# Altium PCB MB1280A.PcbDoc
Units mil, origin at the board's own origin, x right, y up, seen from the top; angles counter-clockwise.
Board outline 2150 x 1780 mil, 2 copper layers (Top Layer, Bottom Layer), stack 61.855 mil thick; 27 components, 23 nets, 119 pads, 19 vias.
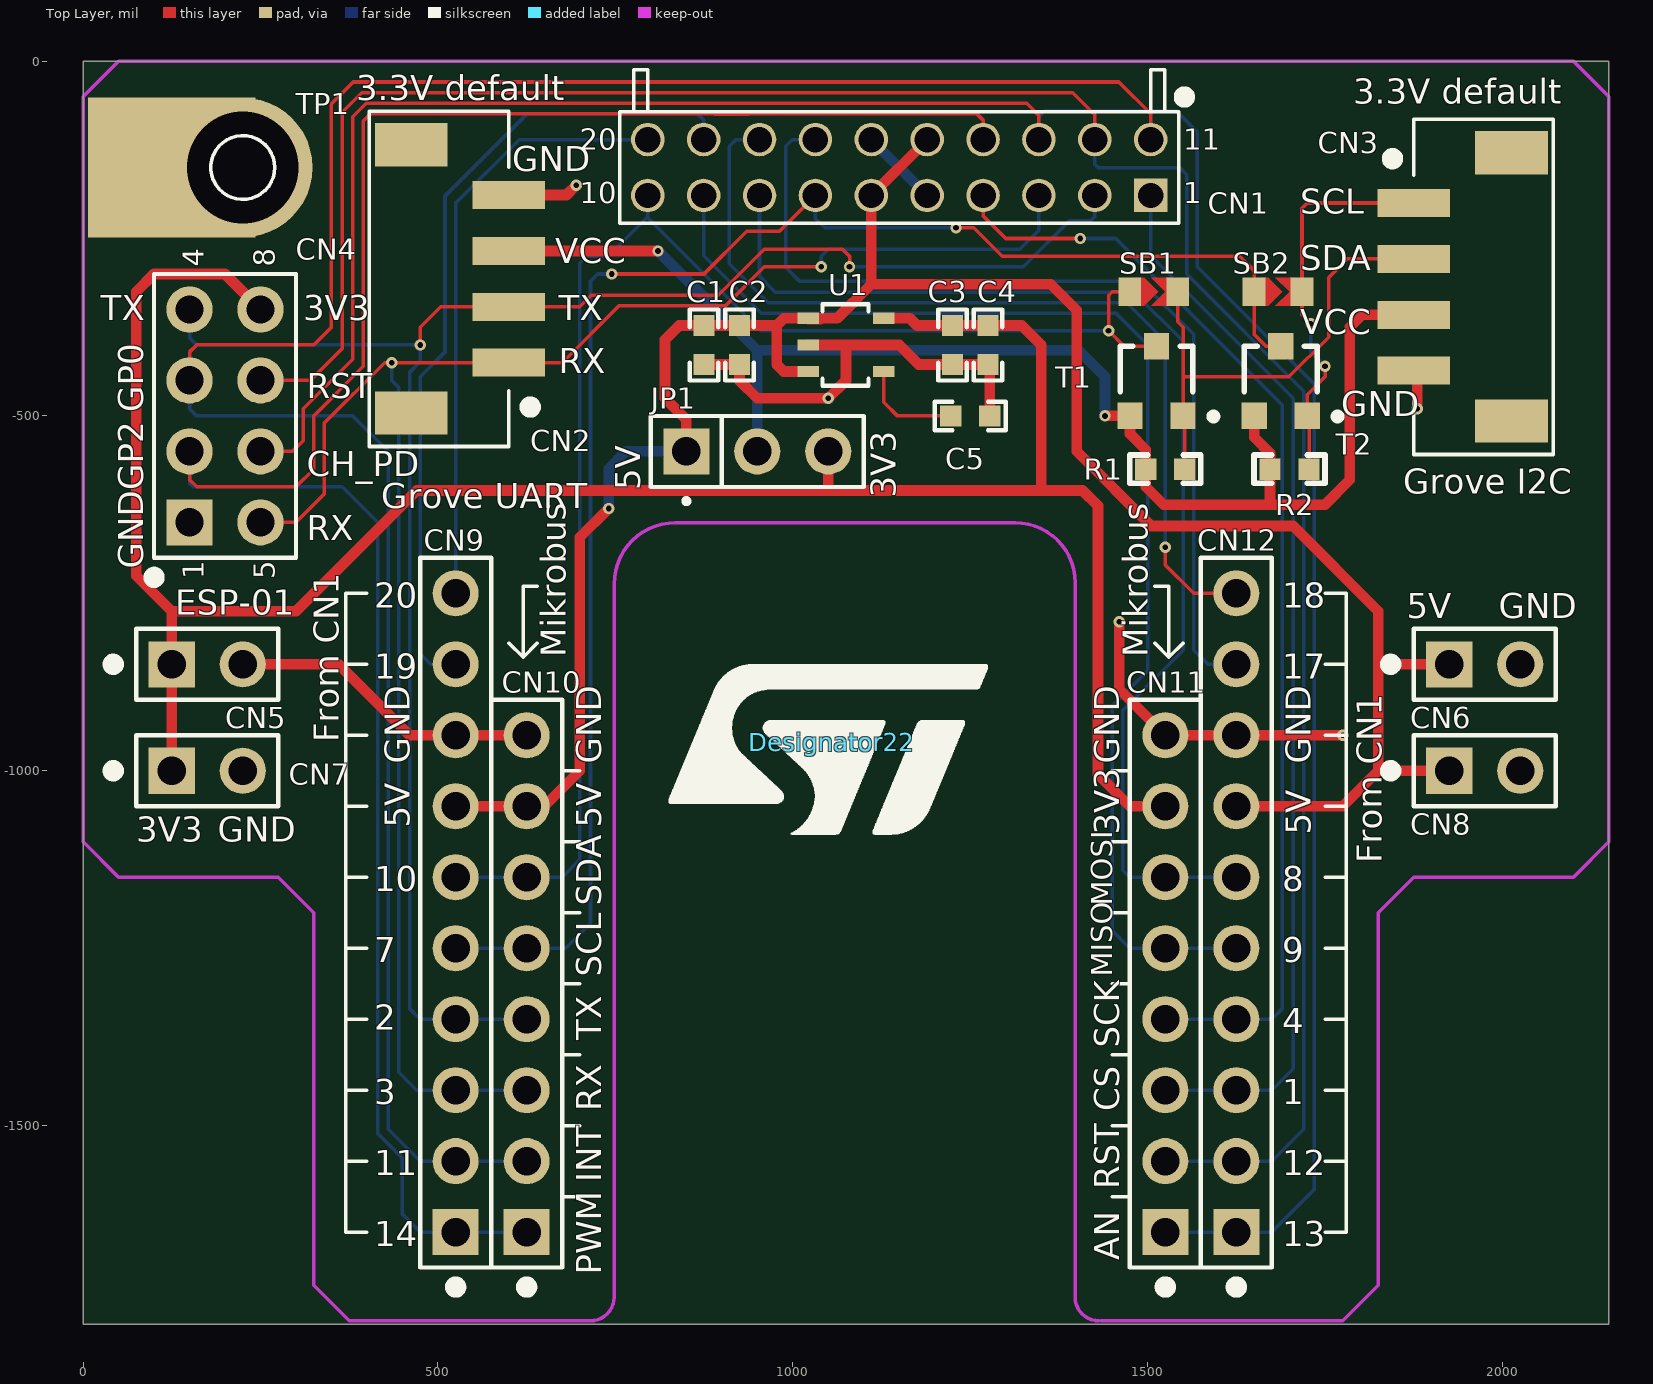
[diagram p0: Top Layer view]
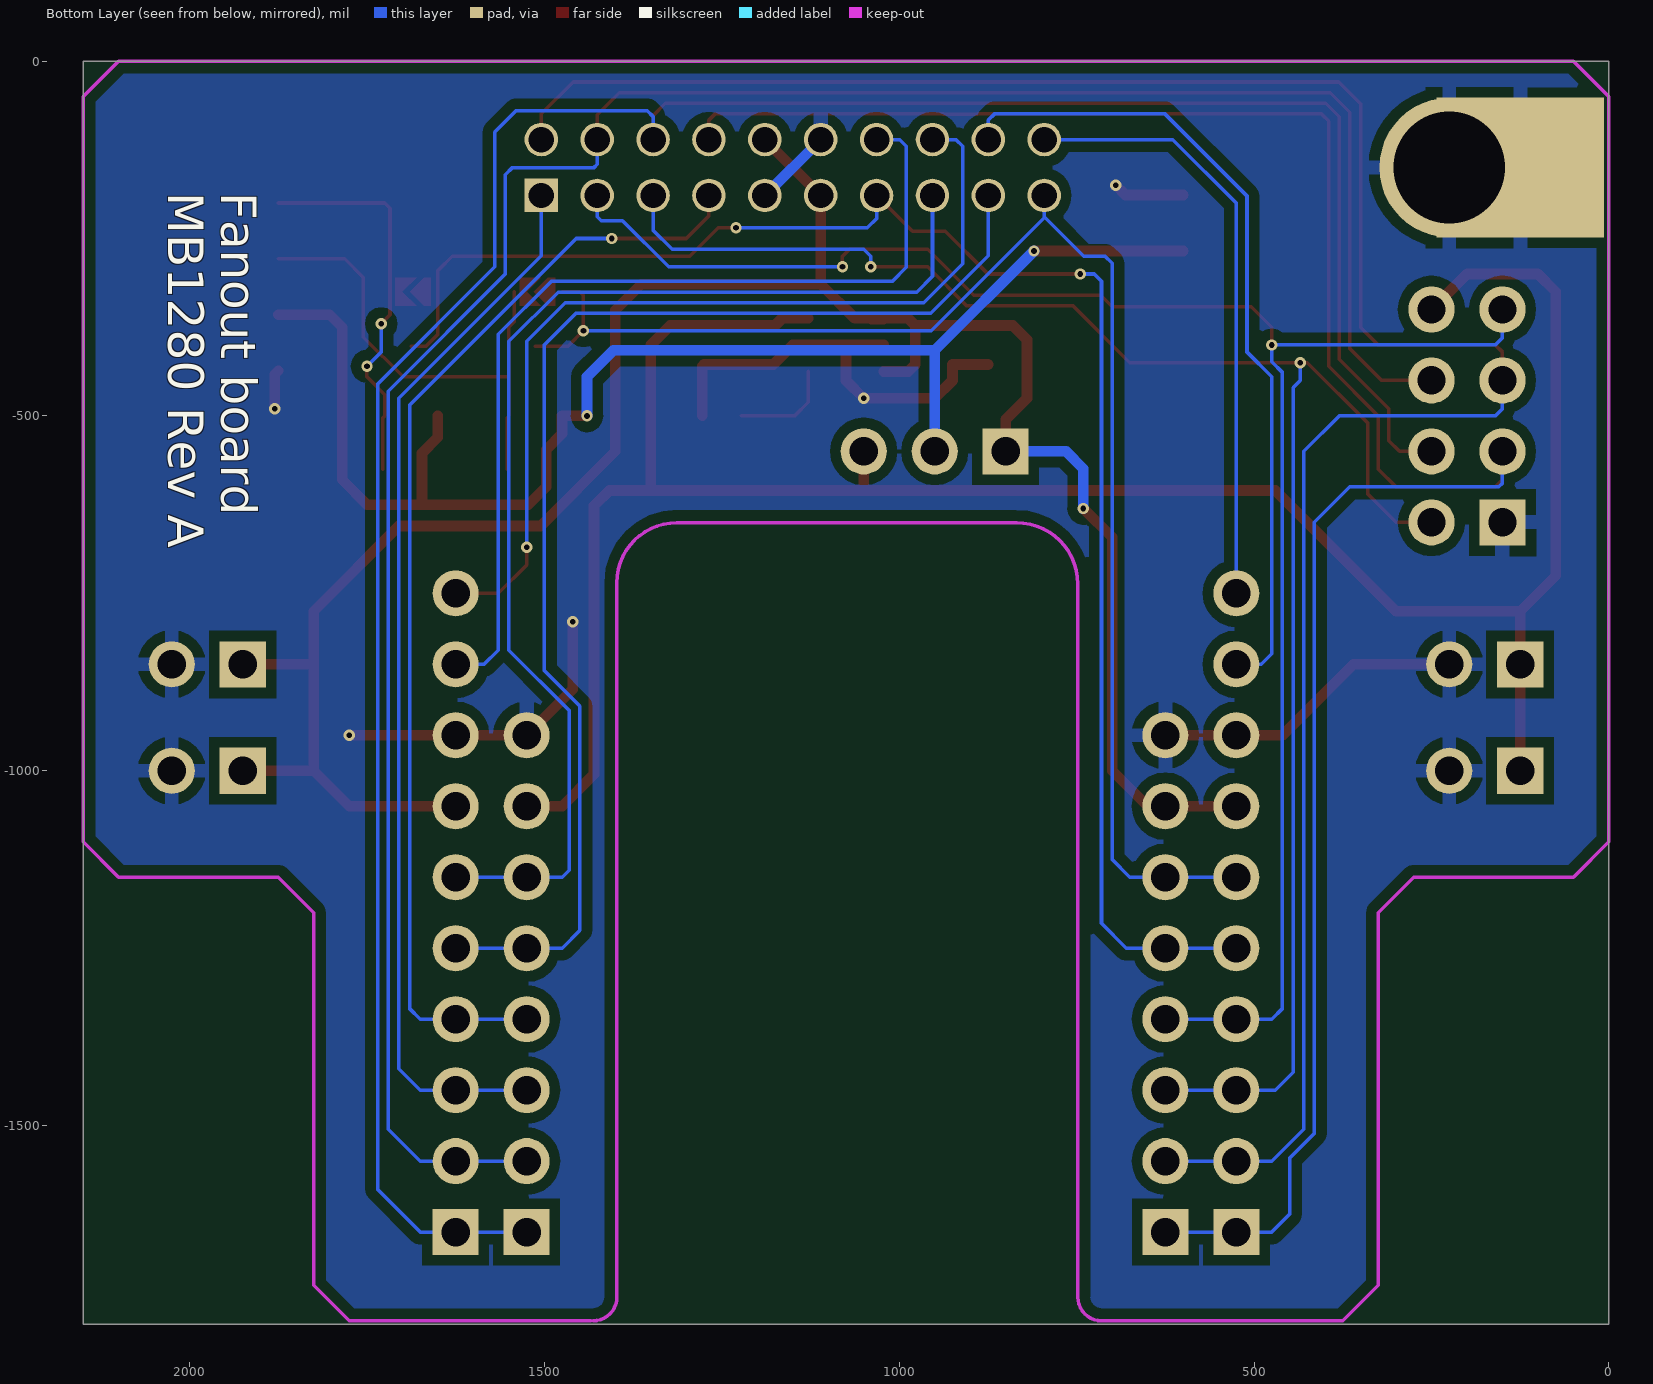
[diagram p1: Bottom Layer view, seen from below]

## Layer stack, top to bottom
Top Solder: solder mask 0.4, Solder Resist, Dk 3.5
Top Layer: signal copper 1.4
Dielectric1: core 59.0551, FR-4, Dk 4.8
Bottom Layer: signal copper 1.4
Bottom Solder: solder mask 0.4, Solder Resist, Dk 3.5

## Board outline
0,0 0,-1100 0,-1780 0,0 2150,0 2150,-1780 1290,-1780 0,-1780

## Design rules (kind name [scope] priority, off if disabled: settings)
Clearance Clearance_1 [(InPoly)] p1: gap=15
Clearance Clearance_2 [(HasFootprint('SB_DIP')) or (HasFootprint('JP2_SMD')) or InNet('PC13')] p2: gap=5
Clearance [All] p3: gap=10
FabricationTestPointUsage TestPointUsage [All] p1: valid=0 allowmultiple=FALSE
FabricationTestpoint Testpoint [(IsPad And (OnTopLayer Or OnBottomLayer))] p1: side=3 testpointundercomponent=TRUE minsize=40 maxsize=100 preferedsize=60 minholesize=0 maxholesize=40 preferedholesize=32 testpointgrid=1 allowsidetop=TRUE allowsidebottom=TRUE usegrid=TRUE gridtolerance=0.01
HoleSize [All] p1: absolutevalues=TRUE maxlimit=150 minlimit=1 maxpercent=80.000 minpercent=20.000
PolygonConnect PolygonConnect_1 [IsVia] p1: connectstyle=Direct reliefconductorwidth=20 reliefentries=4 polygonreliefangle="90 Angle" airgapwidth=10
PolygonConnect [All] p2: connectstyle=Relief reliefconductorwidth=20 reliefentries=4 polygonreliefangle="90 Angle" airgapwidth=10
RoutingLayers [All] p1: top layer_v5=FALSE bottom layer_v5=FALSE
RoutingVias [All] p1: holewidth=13 width=25 viastyle="Through Hole" minholewidth=8 minwidth=16 maxholewidth=28 maxwidth=50
SilkToSolderMaskClearance SilkscreenOverComponentPads [IsPad] p1: minsilkscreentomaskgap=10 clearancetoexposedcopper=TRUE
SolderMaskExpansion [All] p1: expansion=4
Width Width_1 [InNet('VDD_MCU')] p1: maxlimit=100 minlimit=6 preferedwidth=12
Width [All] p2: maxlimit=100 minlimit=5 preferedwidth=5 minimp=50.000000 maximp=50.000000 favimp=50.000000
25 further rules are at their usual default settings.

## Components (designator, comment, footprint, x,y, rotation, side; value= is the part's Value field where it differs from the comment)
C1 "100nF" 0603C 875,-400 r270 top (schematic designator C3)
C2 "1uF_X5R_0603" 0603C 925,-400 r270 top (schematic designator C1)
C3 "1uF_X5R_0603" 0603C 1225,-400 r90 top (schematic designator C2)
C4 "100nF" 0603C 1275,-400 r270 top
C5 "10nF_X7R_0603" 0603C 1250,-500 r0 top
CN1 "TMM-110-01-L-D-RA" 2*10_MALE_2MM_H 1150,-150 r0 top
CN2 "1125S-SMT-4P" 1X4_MALE_C 600,-425 r270 top (schematic designator CN10)
CN3 "1125S-SMT-4P" 1X4_MALE_C 1875,-200 r90 top (schematic designator CN2)
CN4 "Header 4X2A" HDR2X4_CEN1 150,-650 r90 top (schematic designator CN6)
CN5 "PAD 2" HDR_2X1_2R54 125,-850 r0 top
CN6 "PAD 2" HDR_2X1_2R54 1925,-850 r0 top (schematic designator CN7)
CN7 "PAD 2" HDR_2X1_2R54 125,-1000 r0 top (schematic designator CN11)
CN8 "PAD 2" HDR_2X1_2R54 1925,-1000 r0 top (schematic designator CN12)
CN9 "PAD 1X8" 1*10P_FEMALE 525,-1650 r90 top (schematic designator CN4)
CN10 "Header 8X1_Female" 1*8P_FEMALE 625,-1650 r90 top (schematic designator CN9)
CN11 "Header 8X1_Female" 1*8P_FEMALE 1525,-1650 r90 top (schematic designator CN8)
CN12 "PAD 1X8" 1*10P_FEMALE 1625,-1650 r90 top (schematic designator CN3)
Designator22 "Comment" ST_LOGO_10mm 1055,-960 r0 top
JP1 "" SIP3 850,-550 r0 top
R1 "4K7[N/A]" 0603R 1525,-575 r0 top
R2 "4K7[N/A]" 0603R 1700,-575 r0 top
SB1 "Closed" SB_0603 1475,-325 r180 top (schematic designator SB2)
SB2 "Closed" SB_0603 1650,-325 r180 top (schematic designator SB1)
T1 "BSN20[N/A]" SOT23-213 1550,-500 r0 top (schematic designator TR2)
T2 "BSN20[N/A]" SOT23-213 1725,-500 r0 top (schematic designator TR1)
TP1 "Ground" TP_C4MM_PAD 225,-150 r0 top
U1 "LDK120M33R" SOT-23-5L 1075,-400 r0 top

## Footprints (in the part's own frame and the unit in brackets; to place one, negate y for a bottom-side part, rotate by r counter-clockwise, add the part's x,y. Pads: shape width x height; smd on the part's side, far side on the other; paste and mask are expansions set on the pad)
1*8P_FEMALE [mil]
  rect 65x65 hole 40: 1(0,0)
  round 65 hole 40: 2(100,0) 3(200,0) 4(300,0) 5(400,0) 6(500,0) 7(600,0) 8(700,0)
  silkscreen extent -85,-50 750,50
1*10P_FEMALE [mil]
  rect 65x65 hole 40: 1(0,0)
  round 65 hole 40: 2(100,0) 3(200,0) 4(300,0) 5(400,0) 6(500,0) 7(600,0) 8(700,0) 9(800,0) 10(900,0)
  silkscreen extent -85,-50 950,50
1X4_MALE_C [mm] "Connector; Header; 4 Position"
  rect 1.55x2.6 smd: 0(-7.8,-3.5) 0(1.8,-3.5)
  rect 1x2.6 smd: 1(0,0) 2(-2,0) 3(-4,0) 4(-6,0)
  silkscreen extent -9,-5 3,0.95
2*10_MALE_2MM_H [mm]
  rect 1.2x1.2 hole 0.91: 1(9,-1)
  round 1.2 hole 0.91: 2(7,-1) 3(5,-1) 4(3,-1) 5(1,-1) 6(-1,-1) 7(-3,-1) 8(-5,-1) 9(-7,-1) 10(-9,-1) 11(9,1) 12(7,1) 13(5,1) 14(3,1) 15(1,1) 16(-1,1) 17(-3,1) 18(-5,1) 19(-7,1) 20(-9,1)
  silkscreen extent -10,-2 10.4,3.5
0603C [mil]
  rect 30x30 smd: 1(27.5,0) 2(-27.5,0)
  silkscreen extent -50,-20 50,20
0603R [mil]
  rect 30x30 smd: 1(27.5,0) 2(-27.5,0)
  silkscreen extent -50,-20 50,20
HDR2X4_CEN1 [mil] "Connector; Header; 4x2 Position"
  rect 65x65 hole 40: 1(0,0)
  round 65 hole 40: 2(100,0) 3(200,0) 4(300,0) 5(0,-100) 6(100,-100) 7(200,-100) 8(300,-100)
  silkscreen extent -85,-150 350,57
HDR_2X1_2R54 [mil]
  rect 65x65 hole 40: 1(0,0)
  round 65 hole 40: 2(100,0)
  silkscreen extent -90,-50 150,50
SB_0603 [mil]
  rect 32x40 smd: 1(0,0) 2(-67.5,0)
  Top Layer region: -10,20 -20,20 -40,0 -20,-20 -10,-20
  Top Layer region: -60,0 -50,0 -30,20 -60,20
  Top Layer region: -60,0 -50,0 -30,-20 -60,-20
SIP3 [mil]
  rect 65x65 hole 40: 1(0,0)
  round 65 hole 40: 2(100,0) 3(200,0)
  silkscreen extent -50,-72 250,50
SOT23-213 [mm]
  rect 0.9x0.95 smd: 1(0,0) 2(-1.9,0) 3(-0.95,2.5)
  silkscreen extent -2.25,-0.14 1.21,2.5
SOT-23-5L [mil]
  rect 30x16 smd: 1(-53.15,37.4) 2(-53.15,0) 3(-53.15,-37.4) 4(53.15,-37.4) 5(53.15,37.4)
  silkscreen extent -33,-58 32,57
ST_LOGO_10mm [mil]
  silkscreen extent -230,-130 220,110
TP_C4MM_PAD [mm]
  rect 6x5 smd: 1(-2.54,0)
  rect 6x5 smd far side: 1(-2.54,0)
  round 5 hole 4: 1(0,0)
  silkscreen extent -1.14,-1.14 1.14,1.14

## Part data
C1 C4: library part Capacitor_ST, "Capacitor 0402 / 0603 / 0805"
C2 C3: library part "CAP SMD 0603  X5R 1µF 25V 10%", "0603  X5R 1?"
C5: library part "CAP SMD 0603  X7R 10000PF 50V 10%", "0603  X7R 10NF"
CN1: library part "Header 10X2A", "Header, 10-Pin, Dual row"
CN2 CN3: library part "Header 4"
CN4: "Header, 4-Pin, Dual row"
CN5 CN6 CN7 CN8: library part "Header 2", "Header, 2-Pin"
CN9 CN12: library part "Header 10X1_Female", "Header, 10-Pin, Single row,female"
CN10 CN11: "Header, 8-Pin, Single row,female"
JP1: library part Jumper3
R1 R2: library part res1, "Resistor"
SB1 SB2: library part "Circuit Breaker", "Circuit Breaker"
T1 T2: library part 2N7000
TP1: library part TP
U1: "200 mA low quiescent current very low noise LDO"

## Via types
v1: diameter 16, hole 8, Top Layer to Bottom Layer, tented both sides, 19 vias

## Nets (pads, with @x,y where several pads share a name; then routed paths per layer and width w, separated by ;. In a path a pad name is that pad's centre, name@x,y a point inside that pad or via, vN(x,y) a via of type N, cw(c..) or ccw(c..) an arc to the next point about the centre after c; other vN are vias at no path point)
+3V3: C3.1 C4.2 CN4.8 CN5.1 CN7.1 CN11.7 JP1.3 U1.5 | length 3275.5
  Top Layer w15: CN7.1 CN5.1 125,-775 ; CN4.8 200,-300 100,-300 75,-325 75,-725 125,-775 ; JP1.3 1050,-605 ; U1.5 1165.1,-362.6 1175,-372.5 C3.1 C4.2 1322.5,-372.5 1350,-400 1350,-605 ; CN11.7 1475,-1050 1430,-1005 1430,-626.72 1408.28,-605 1350,-605 ; 125,-775 300,-775 470,-605 1050,-605 ; 1050,-605 1350,-605
+5V: C1.2 C2.2 CN1.6 CN1.15 CN6.1 CN8.1 CN9.7 CN10.7 CN12.7 JP1.1 U1.1 U1.3 | length 3257.3
  Top Layer w15: CN9.7 CN10.7 650,-1050 700,-1000 700,-700 700,-671.01 v1(740.51,-630.5) ; JP1.1 850,-505 820,-475 820,-392.5 840,-372.5 C1.2 C2.2 977.5,-372.5 ; U1.3 987.4,-437.4 977.5,-427.5 977.5,-372.5 ; U1.1 987.4,-362.6 977.5,-372.5 ; U1.1@1022.66,-363.41 1038.64,-363.41 1039.45,-362.6 1062.4,-362.6 1110.63,-314.37 ; CN1.15 CN1.6 1110.63,-314.37 ; CN12.7 1775,-1050 1825,-1000 ; CN8.1 1825,-1000 ; CN6.1 1825,-850 ; 1110.63,-314.37 1363.31,-314.37 1400,-351.06 1400,-550 1505,-655 1705,-655 1825,-775 1825,-850 ; 1825,-1000 1825,-850
  Bottom Layer w15: v1(740.51,-630.5) 740.51,-574.49 765,-550 821.01,-550 JP1.1
GND: C1.1 C2.1 C3.2 C4.1 C5.1 CN1.5 CN1.16 CN2.4 CN3.4 CN4.1 CN5.2 CN6.2 CN7.2 CN8.2 CN9.8 CN10.8 CN11.8 CN12.8 TP1.1 U1.2 | length 1777.5
  Top Layer w15: CN5.2 360,-850 460,-950 CN9.8 CN10.8 ; CN2.4 681.22,-188.78 v1(695,-175) ; C1.1 C2.1 925,-450 950,-475 v1(1050,-475) 1075,-450 1075,-400 ; U1.2 1075,-400 ; C5.1 1277.5,-430 C4.1 C3.2 1177.5,-427.5 1150,-400 1075,-400 ; v1(1460,-790) 1460,-885 CN11.8 CN12.8 v1(1775,-950) ; CN3.4 1880,-441.22 v1(1880,-490)
  Bottom Layer w15: CN1.16 CN1.5
I2C_SCL: CN3.1 R2.1 SB2.2 T2.1 | length 553
  Top Layer w5: R2.1 1727.5,-502.5 T2.1 1725,-470 1750,-445 v1(1750,-430) ; v1(1730,-370) 1717.5,-357.5 SB2.2 1717.5,-207.5 1725,-200 CN3.1
  Bottom Layer w5: v1(1730,-370) 1730,-410 v1(1750,-430)
I2C_SDA: CN3.2 R1.1 SB1.2 T1.1 | length 697.2
  Top Layer w5: SB1.2 1542.5,-367.5 1550,-375 1550,-445 ; R1.1 1552.5,-502.5 T1.1 1550,-445 ; CN3.2 1781.26,-278.74 1755,-305 1755,-388.94 1698.94,-445 1550,-445
NetC5_2: C5.2 U1.4 | length 145.6
  Top Layer w5: U1.4 1128.15,-480.65 1147.5,-500 C5.2
PMOD#1: CN1.1 CN11.3 CN12.3 | length 1506.2
  Bottom Layer w5: CN1.1 1504.33,-274.33 1705,-475 1705,-1420 1675,-1450 CN12.3 CN11.3
PMOD#2: CN1.2 CN2.2 CN4.4 CN9.4 CN10.4 | length 2581.1
  Top Layer w5: v1(475,-400) 475,-375 503.74,-346.26 CN2.2 700,-346.26 716.26,-330 895,-330 960,-265 1070,-265 1080,-275 v1(1080,-290)
  Bottom Layer w5: CN4.4 150,-390 160,-400 v1(475,-400) 475,-423.79 460,-438.79 460,-1335 475,-1350 CN9.4 CN10.4 ; v1(1080,-290) 1324.96,-290 1389.96,-225 1420,-225 1425.59,-219.41 CN1.2
PMOD#3: CN1.3 CN2.1 CN4.5 CN9.3 CN10.3 | length 2578.1
  Top Layer w5: CN4.5 300,-650 340,-610 340,-510 425,-425 v1(435,-425) CN2.1 675,-425 755,-345 905,-345 960,-290 v1(1040,-290)
  Bottom Layer w5: v1(435,-425) 435,-450 445,-460 445,-1425 470,-1450 CN9.3 CN10.3 ; v1(1040,-290) 1040,-275 1050,-265 1320,-265 1346.85,-238.15 CN1.3
PMOD#4: CN1.4 CN11.4 CN12.4 | length 1582.4
  Top Layer w5: CN1.4 1268.11,-218.11 1300,-250 v1(1405,-250)
  Bottom Layer w5: v1(1405,-250) 1455,-250 1690,-485 1690,-1335 1675,-1350 CN12.4 CN11.4
PMOD#7: CN1.7 CN9.5 CN10.5 SB2.1 T2.3 | length 2291.7
  Top Layer w5: v1(745,-300) 875,-300 935,-240 981.26,-240 CN1.7 ; v1(1230,-235) 1255,-235 1295,-275 1630,-275 1650,-295 SB2.1 1650,-385 1666.58,-401.58 T2.3
  Bottom Layer w5: CN9.5 CN10.5 680,-1250 715,-1215 715,-310 725,-300 v1(745,-300) ; CN1.7 1031.89,-221.89 1045,-235 v1(1230,-235)
PMOD#8: CN1.8 CN11.6 CN12.6 | length 1693
  Bottom Layer w5: CN1.8 953.15,-303.15 975.5,-325.5 1480.5,-325.5 1550,-395 1550,-830 1465,-915 1465,-1140 1475,-1150 CN11.6 CN12.6
PMOD#9: CN1.9 CN11.5 CN12.5 | length 1793.7
  Bottom Layer w5: CN1.9 874.41,-274.41 955.5,-355.5 1455.5,-355.5 1500,-400 1500,-858.79 1450,-908.79 1450,-1225 1475,-1250 CN11.5 CN12.5
PMOD#10: CN1.10 CN9.6 CN10.6 SB1.1 T1.3 | length 2052.9
  Top Layer w5: SB1.1 1450,-325 1445,-330 v1(1445,-380) 1466.58,-401.58 T1.3
  Bottom Layer w5: CN9.6 CN10.6 675,-1150 700,-1125 700,-285.04 710.04,-275 740,-275 794.33,-220.67 795.67,-220.67 ; CN1.10 795.67,-220.67 ; v1(1445,-380) 955,-380 795.67,-220.67
PMOD#11: CN1.11 CN4.3 CN9.2 CN10.2 | length 3304.8
  Top Layer w5: CN4.3 150,-410 160,-400 325,-400 350,-375 350,-60 380.49,-29.51 1459.51,-29.51 1504.33,-74.33 CN1.11
  Bottom Layer w5: CN4.3 150,-490 160,-500 380,-500 430,-550 430,-1505 475,-1550 CN9.2 CN10.2
PMOD#12: CN1.12 CN4.7 CN11.2 CN12.2 | length 3383.8
  Top Layer w5: CN4.7 320,-450 365,-405 365,-72.08 392.57,-44.51 1394.51,-44.51 1425.59,-75.59 CN1.12
  Bottom Layer w5: CN1.12 1425.59,-145.59 1430,-150 1545,-150 1555,-160 1555,-300 1720,-465 1720,-1505 1675,-1550 CN12.2 CN11.2
PMOD#13: CN1.13 CN4.6 CN11.1 CN12.1 | length 3632.1
  Top Layer w5: CN4.6 295,-550 310,-535 310,-490 380,-420 380,-78.29 398.79,-59.51 1329.51,-59.51 1346.85,-76.85 CN1.13
  Bottom Layer w5: CN1.13 1346.85,-78.15 1355,-70 1540,-70 1570,-100 1570,-290 1735,-455 1735,-1590 1675,-1650 CN12.1 CN11.1
PMOD#14: CN1.14 CN4.2 CN9.1 CN10.1 | length 3165.4
  Top Layer w5: CN4.2 150,-590 160,-600 300,-600 325,-575 325,-500 395,-430 395,-84.51 405,-74.51 889.37,-74.51 889.86,-75 937.7,-75 938.19,-74.51 1259.51,-74.51 1268.11,-83.11 CN1.14
  Bottom Layer w5: CN4.2 150,-595 155,-600 365,-600 415,-650 415,-1511.21 450,-1546.21 450,-1625 475,-1650 CN9.1 CN10.1
PMOD#17: CN1.17 CN12.9 | length 1343.7
  Bottom Layer w5: CN1.17 999.37,-110.63 990,-120 990,-290.5 1010,-310.5 1490.5,-310.5 1565,-385 1565,-830 1585,-850 CN12.9
PMOD#18: CN1.18 CN12.10 | length 1303.4
  Top Layer w5: v1(1525,-685) 1525,-710 1565,-750 CN12.10
  Bottom Layer w5: CN1.18 919.9,-110.63 910.53,-120 910.53,-285.53 965.5,-340.5 1470.5,-340.5 1525,-395 v1(1525,-685)
PMOD#19: CN1.19 CN9.9 | length 1159.1
  Bottom Layer w5: CN9.9 490,-850 475,-835 475,-445 510,-410 510,-190 625.49,-74.51 865.83,-74.51 874.41,-83.08 CN1.19
PMOD#20: CN1.20 CN9.10 | length 857.7
  Bottom Layer w5: CN9.10 525,-200 614.37,-110.63 CN1.20
VCC: CN2.3 CN3.3 JP1.2 R1.2 R2.2 T1.2 T2.2 | length 2011.8
  Top Layer w15: CN2.3 v1(810,-267.52) ; v1(1440,-500) T1.2 1475.2,-525.2 1497.5,-547.5 R1.2 1497.5,-600 1522.5,-625 1750,-625 1785,-590 1785,-375 1802.52,-357.48 CN3.3 ; T2.2 1650.2,-530.2 1672.5,-552.5 R2.2 1672.5,-622.5
  Bottom Layer w15: v1(810,-267.52) 950,-407.52 ; JP1.2 950,-407.52 ; v1(1440,-500) 1440,-445 1402.52,-407.52 950,-407.52
pads on no net: CN2.0 CN3.0

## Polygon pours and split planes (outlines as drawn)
GND on Bottom Layer "Bottom Layer-No Net" (solid, remove dead copper, pour order 4): 10,-10 10,-1785 1625,-1785 2230,-1785 2160,-1715 2160,-1085 2160,-10 15,-10

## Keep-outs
Keep-Out Layer:
  lines w5: 1431.25,-1775 cw(c1431.25,-1741.68) 1397.93,-1741.68 1397.93,-1280.32 1397.93,-734.98 ccw(c1313.34,-734.98) 1313.34,-650.39 834.72,-650.39 ccw(c834.72,-736.79) 748.32,-736.79 748.32,-1280.32 748.32,-1741.68 cw(c715,-1741.68) 715,-1775 375,-1775 325,-1725 325,-1200 275,-1150 50,-1150 0,-1100 0,-50 50,0 2100,0 2150,-50 2150,-1100 2100,-1150 1875,-1150 1825,-1200 1825,-1725 1775,-1775 1435,-1775

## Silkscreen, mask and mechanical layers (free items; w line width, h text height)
Top Overlay:
  lines w5: 370,-1550 400,-1550 ; 370,-1450 400,-1450 ; 370,-1350 400,-1350 ; 370,-1250 400,-1250 ; 370,-1150 400,-1150 ; 370,-1050 400,-1050 ; 370,-950 400,-950 ; 370,-850 400,-850 ; 400,-1650 370,-1650 370,-750 400,-750 ; 600,-820 620,-840 ; 640,-820 620,-840 ; 640,-740 620,-740 620,-840 ; 675,-1600 700,-1600 ; 675,-1500 700,-1500 ; 675,-1400 700,-1400 ; 675,-1300 700,-1300 ; 675,-1200 700,-1200 ; 675,-1100 700,-1100 ; 675,-1000 700,-1000 ; 1450,-1600 1475,-1600 ; 1450,-1500 1475,-1500 ; 1450,-1400 1475,-1400 ; 1450,-1300 1475,-1300 ; 1450,-1200 1475,-1200 ; 1450,-1100 1475,-1100 ; 1450,-1000 1475,-1000 ; 1510,-820 1530,-840 ; 1510,-740 1530,-740 1530,-840 ; 1550,-820 1530,-840 ; 1750,-1650 1780,-1650 1780,-750 1750,-750 ; 1750,-1550 1780,-1550 ; 1750,-1450 1780,-1450 ; 1750,-1350 1780,-1350 ; 1750,-1250 1780,-1250 ; 1750,-1150 1780,-1150 ; 1750,-1050 1780,-1050 ; 1750,-950 1780,-950 ; 1750,-850 1780,-850
  text "3.3V default" at 385,-55 h35
  text "3.3V default" at 1790,-60 h35
  text "GND" at 605,-155 h35
  text "SCL" at 1715,-215 h35
  text "VCC" at 665,-285 h35
  text "SDA" at 1715,-295 h35
  text "TX" at 25,-365 h35
  text "3V3" at 310,-365 h35
  text "TX" at 670,-365 h35
  text "VCC" at 1715,-385 h35
  text "RX" at 670,-440 h35
  text "RST" at 315,-475 h35
  text "GP0" at 85,-495 h35 r90
  text "GND" at 1772.6,-500.79 h35
  text "CH_PD" at 315,-585 h35
  text "GP2" at 85,-605 h35 r90
  text "5V" at 785,-605 h35 r90
  text "Grove I2C" at 1860,-610 h35
  text "3V3" at 1145,-615 h35 r90
  text "Grove UART" at 420,-630 h35
  text "RX" at 315,-675 h35
  text "GND" at 85,-715 h35 r90
  text "20" at 410,-770 h35
  text "18" at 1690,-770 h35
  text "ESP-01" at 130,-780 h35
  text "5V" at 1865,-785 h35
  text "GND" at 1995,-785 h35
  text "Mikrobus" at 680,-840 h35 r90
  text "Mikrobus" at 1500,-840 h35 r90
  text "19" at 410,-870 h35
  text "17" at 1690,-870 h35
  text "From CN1" at 360,-960 h35 r90
  text "GND" at 460,-990 h35 r90
  text "GND" at 730,-990 h35 r90
  text "GND" at 1460,-990 h35 r90
  text "GND" at 1730,-990 h35 r90
  text "5V" at 460,-1080 h35 r90
  text "5V" at 730,-1080 h35 r90
  text "3V3" at 1460,-1090 h35 r90
  text "5V" at 1730,-1090 h35 r90
  text "3V3" at 75,-1100 h35
  text "GND" at 190,-1100 h35
  text "From CN1" at 1830,-1130 h35 r90
  text "10" at 410,-1170 h35
  text "8" at 1690,-1170 h35
  text "SDA" at 730,-1190 h35 r90
  text "MOSI" at 1450,-1190 h30 r90
  text "7" at 410,-1270 h35
  text "9" at 1690,-1270 h35
  text "SCL" at 730,-1290 h35 r90
  text "MISO" at 1450,-1290 h30 r90
  text "2" at 410,-1365 h35
  text "4" at 1690,-1370 h35
  text "TX" at 730,-1380 h35 r90
  text "SCK" at 1460,-1390 h35 r90
  text "3" at 410,-1470 h35
  text "1" at 1690,-1470 h35
  text "RX" at 730,-1480 h35 r90
  text "CS" at 1460,-1480 h35 r90
  text "11" at 410,-1570 h35
  text "12" at 1690,-1570 h35
  text "INT" at 730,-1580 h35 r90
  text "RST" at 1460,-1590 h35 r90
  text "14" at 410,-1670 h35
  text "13" at 1690,-1670 h35
  text "AN" at 1460,-1690 h35 r90
  text "PWM" at 730,-1710 h35 r90
Bottom Overlay:
  text "Fanout board" at 1955,-185 h50 r90
  text "MB1280 Rev A" at 2030,-185 h50 r90
Mechanical 1:
  lines w5: 749.41,-1280.32 749.41,-1741.68 cw(c716.09,-1741.68) 716.09,-1775 375,-1775 325,-1725 325,-1200 275,-1150 50,-1150 0,-1100 0,-50 50,0 2100,0 2150,-50 2150,-1100 2100,-1150 1875,-1150 1825,-1200 1825,-1725 1775,-1775 1432.34,-1775 cw(c1432.34,-1741.68) 1399.02,-1741.68 1399.02,-1280.32 ; 749.41,-1278.94 cw(c769.09,-1278.94) 788.78,-1278.94 ; 788.78,-1280.32 788.78,-1741.68 ccw(c822.1,-1741.68) 822.1,-1775 1326.32,-1775 ccw(c1326.32,-1741.68) 1359.65,-1741.68 1359.65,-1280.32 ; 1359.65,-1278.94 cw(c1379.33,-1278.94) 1399.02,-1278.94 ; 749.41,-1150.39 ccw(c769.09,-1150.39) 788.78,-1150.39 788.78,-728.74 cw(c835.63,-728.74) 835.63,-681.89 1312.8,-681.89 cw(c1312.8,-728.74) 1359.65,-728.74 1359.65,-1150.39 ccw(c1379.33,-1150.39) 1399.02,-1150.39 1399.02,-734.98 ccw(c1314.43,-734.98) 1314.43,-650.39 835.8,-650.39 ccw(c835.8,-736.79) 749.41,-736.79 749.41,-1150.39
  text "MB1280" at 120,145 h60
Drill Drawing:
  lines w1: 2455,-1482.83 2875,-1482.83 ; 2455,-1469.53 2875,-1469.53 ; 2395,-1546 ccw(c2399,-1546) 2399,-1550 2931,-1550 ccw(c2931,-1546) 2935,-1546 2935,-1454 ccw(c2931,-1454) 2931,-1450 2399,-1450 ccw(c2399,-1454) 2395,-1454 2395,-1546
  text ".legend" at 2475,-360 h40
  text "Layer Stack Up Detail for: MB1280.PcbDoc" at 2455,-1464.87 h7
  text "Layer" at 2455,-1474.53 h3
  text "Gerber" at 2542.98,-1474.53 h3
  text "Copper" at 2594.57,-1474.53 h3
  text "Dielectric" at 2651.06,-1474.53 h3
  text "Dielectric" at 2709.64,-1474.53 h3
  text "Dielectric" at 2777.63,-1474.53 h3
  text "Dielectric" at 2836.22,-1474.53 h3
  text "Name" at 2455,-1480.53 h3
  text "Document" at 2542.98,-1480.53 h3
  text "Thickness" at 2594.57,-1480.53 h3
  text "Height" at 2651.06,-1480.53 h3
  text "Material" at 2709.64,-1480.53 h3
  text "Constant" at 2777.63,-1480.53 h3
  text "Type" at 2836.22,-1480.53 h3
  text "Top Solder Mask" at 2455,-1489.58 h4
  text "(.GTS)" at 2542.98,-1489.58 h4
  text "0.4mil" at 2651.06,-1489.58 h4
  text "Solder Resist" at 2709.64,-1489.58 h4
  text "3.50" at 2777.63,-1489.58 h4
  text "Top Layer" at 2455,-1502.08 h4
  text "(.GTL)" at 2542.98,-1502.08 h4
  text "1.4mil" at 2594.57,-1502.08 h4
  text "59.055mil" at 2651.06,-1508.33 h4
  text "FR-4" at 2709.64,-1508.33 h4
  text "4.80" at 2777.63,-1508.33 h4
  text "Core" at 2836.22,-1508.33 h4
  text "Bottom Layer" at 2455,-1514.58 h4
  text "(.GBL)" at 2542.98,-1514.58 h4
  text "1.4mil" at 2594.57,-1514.58 h4
  text "Bottom Solder Mask" at 2455,-1527.08 h4
  text "(.GBS)" at 2542.98,-1527.08 h4
  text "0.4mil" at 2651.06,-1527.08 h4
  text "Solder Resist" at 2709.64,-1527.08 h4
  text "3.50" at 2777.63,-1527.08 h4

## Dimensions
749.41,-1741.68 to 1399.02,-1741.68 on Drill Drawing
325,-1725 to 1825,-1725 on Drill Drawing
2100,0 to 1775,-1775 on Drill Drawing
0,-50 to 2150,-50 on Drill Drawing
